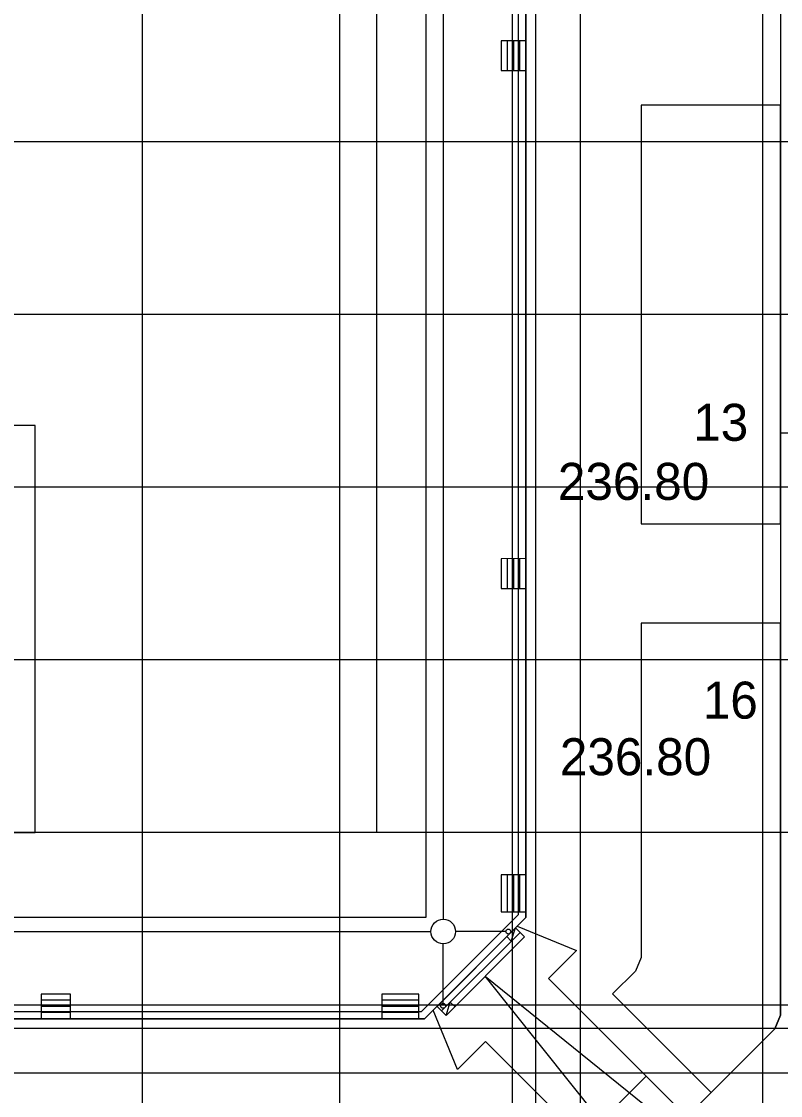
# Model space of a CAD drawing. Extents: x -264031 to -263588, y -1242281 to -1242059.
# Drawn here: x -263832.36 to -263801.59, y -1242227.54 to -1242184 of the extents above; entities that cross this region are included whole.
import ezdxf

# ---------------------------------------------------------------- set-up
doc = ezdxf.new("R2010")
doc.units = 0
for name, color, linetype in [('HESCON_OSI_STAVBY_KFA', 7, 'Continuous'), ('KFA_2D_SITUACIA_DSP', 7, 'Continuous'), ('KFA_BODY_CISLO', 7, 'Continuous'), ('KFA_BODY_VYSKA', 7, 'Continuous')]:
    doc.layers.add(name, color=color, linetype=linetype)

msp = doc.modelspace()

# ---------------------------------------------------------------- linework, layer by layer
at = {"layer": 'HESCON_OSI_STAVBY_KFA'}
for p, q in [((-263827.468, -1242083.237), (-263827.468, -1242246.707)), ((-263819.468, -1242083.237), (-263819.468, -1242246.707)), ((-263812.468, -1242083.237), (-263812.468, -1242246.707)), ((-263811.518, -1242083.237), (-263811.518, -1242246.707)), ((-263809.718, -1242083.237), (-263809.718, -1242246.707)), ((-263802.318, -1242083.237), (-263802.318, -1242246.707)), ((-263792.653, -1242188.882), (-263909.343, -1242188.882)), ((-263792.653, -1242195.882), (-263917.263, -1242195.882)), ((-263792.653, -1242202.882), (-263909.343, -1242202.882)), ((-263792.653, -1242209.882), (-263909.343, -1242209.882)), ((-263792.653, -1242216.882), (-263911.523, -1242216.882)), ((-263792.653, -1242223.882), (-263911.523, -1242223.882)), ((-263792.653, -1242224.832), (-263911.523, -1242224.832)), ((-263792.653, -1242226.632), (-263911.523, -1242226.632))]:
    msp.add_line(p, q, dxfattribs=at)
at = {"layer": 'KFA_2D_SITUACIA_DSP'}
for p, q in [((-263815.263, -1242164.687), (-263815.263, -1242220.396)), ((-263811.918, -1242184.782), (-263812.918, -1242184.782)), ((-263812.918, -1242184.782), (-263812.918, -1242185.982)), ((-263812.668, -1242184.782), (-263812.668, -1242185.982)), ((-263812.418, -1242184.782), (-263812.418, -1242185.982)), ((-263812.168, -1242184.782), (-263812.168, -1242185.982)), ((-263812.918, -1242185.982), (-263811.918, -1242185.982)), ((-263807.243, -1242187.394), (-263807.243, -1242204.369)), ((-263801.593, -1242187.394), (-263807.243, -1242187.394)), ((-263801.593, -1242204.369), (-263801.593, -1242187.394)), ((-263801.593, -1242200.682), (-263800.593, -1242200.682)), ((-263807.243, -1242204.369), (-263801.593, -1242204.369)), ((-263811.924, -1242205.773), (-263812.918, -1242205.782)), ((-263812.918, -1242205.782), (-263812.918, -1242206.982)), ((-263812.668, -1242205.782), (-263812.668, -1242206.982)), ((-263812.418, -1242205.782), (-263812.418, -1242206.982)), ((-263812.168, -1242205.782), (-263812.168, -1242206.982)), ((-263812.918, -1242206.982), (-263811.924, -1242206.991)), ((-263807.243, -1242208.394), (-263807.243, -1242221.942)), ((-263801.593, -1242208.394), (-263807.243, -1242208.394)), ((-263801.593, -1242224.282), (-263801.593, -1242208.394)), ((-263811.939, -1242218.592), (-263812.918, -1242218.592)), ((-263812.918, -1242218.592), (-263812.918, -1242220.092)), ((-263812.668, -1242218.592), (-263812.668, -1242220.092)), ((-263812.418, -1242218.592), (-263812.418, -1242220.092)), ((-263812.168, -1242218.592), (-263812.168, -1242220.092)), ((-263812.918, -1242220.092), (-263811.918, -1242220.092)), ((-263815.516, -1242223.929), (-263812.335, -1242220.747)), ((-263812.506, -1242221.283), (-263812.335, -1242220.747)), ((-263812.151, -1242220.931), (-263812.335, -1242220.747)), ((-263851.668, -1242220.896), (-263815.763, -1242220.896)), ((-263815.334, -1242224.112), (-263812.152, -1242220.929)), ((-263811.968, -1242221.113), (-263815.15, -1242224.295)), ((-263812.725, -1242220.896), (-263814.763, -1242220.896)), ((-263812.504, -1242221.284), (-263812.688, -1242221.101)), ((-263811.968, -1242221.113), (-263812.152, -1242220.929)), ((-263815.27, -1242223.809), (-263815.264, -1242221.396)), ((-263807.243, -1242221.942), (-263807.472, -1242222.496)), ((-263807.472, -1242222.496), (-263808.4, -1242223.424)), ((-263830.369, -1242223.432), (-263831.567, -1242223.432)), ((-263831.567, -1242223.432), (-263831.567, -1242224.432)), ((-263830.369, -1242223.682), (-263831.567, -1242223.682)), ((-263830.369, -1242224.432), (-263830.369, -1242223.432)), ((-263816.259, -1242223.432), (-263817.757, -1242223.432)), ((-263817.757, -1242223.432), (-263817.757, -1242224.432)), ((-263816.259, -1242223.682), (-263817.757, -1242223.682)), ((-263816.259, -1242224.432), (-263816.259, -1242223.432)), ((-263815.15, -1242224.295), (-263814.98, -1242223.758)), ((-263814.797, -1242223.942), (-263814.98, -1242223.758)), ((-263808.4, -1242223.424), (-263804.405, -1242227.419)), ((-263830.369, -1242223.932), (-263831.567, -1242223.932)), ((-263830.369, -1242224.182), (-263831.567, -1242224.182)), ((-263816.259, -1242223.932), (-263817.757, -1242223.932)), ((-263816.259, -1242224.182), (-263817.757, -1242224.182)), ((-263815.333, -1242224.113), (-263815.516, -1242223.929)), ((-263815.15, -1242224.295), (-263815.334, -1242224.112)), ((-263801.822, -1242224.837), (-263801.593, -1242224.282)), ((-263804.405, -1242227.419), (-263801.822, -1242224.837))]:
    msp.add_line(p, q, dxfattribs=at)
for points in [[(-263909.043, -1242125.432), (-263902.343, -1242125.432), (-263902.343, -1242104.482), (-263902.112, -1242103.927), (-263898.54, -1242100.355), (-263895.995, -1242097.81), (-263892.423, -1242094.238), (-263891.868, -1242094.007), (-263812.071, -1242094.007), (-263811.513, -1242094.238), (-263801.823, -1242103.927), (-263801.593, -1242104.482), (-263801.593, -1242224.282), (-263801.824, -1242224.838), (-263805.392, -1242228.407)], [(-263811.918, -1242108.434), (-263811.918, -1242220.33), (-263812.262, -1242220.675), (-263809.862, -1242221.669), (-263810.999, -1242222.806), (-263807.039, -1242226.765), (-263809.585, -1242229.311), (-263813.545, -1242225.351), (-263814.681, -1242226.488), (-263815.675, -1242224.088), (-263816.02, -1242224.432), (-263887.916, -1242224.432)], [(-263807.941, -1242230.956), (-263813.544, -1242225.352), (-263814.681, -1242226.488), (-263815.675, -1242224.088), (-263812.262, -1242220.675)], [(-263812.262, -1242220.675), (-263809.863, -1242221.669), (-263810.999, -1242222.806), (-263805.392, -1242228.407)], [(-263803.204, -1242235.693), (-263813.559, -1242222.704), (-263800.652, -1242233.141)]]:
    msp.add_lwpolyline(points, dxfattribs=at)
for points in [[(-263816.02, -1242224.432), (-263811.918, -1242220.33), (-263811.918, -1242108.434), (-263816.02, -1242104.332), (-263887.916, -1242104.332), (-263892.018, -1242108.434), (-263892.018, -1242147.332), (-263893.618, -1242147.332), (-263893.618, -1242162.382), (-263894.718, -1242162.382), (-263894.718, -1242166.382), (-263893.618, -1242166.382), (-263893.618, -1242181.432), (-263892.018, -1242181.432), (-263892.018, -1242220.33), (-263887.916, -1242224.432)], [(-263816.144, -1242224.132), (-263812.218, -1242220.206), (-263812.218, -1242108.558), (-263816.144, -1242104.632), (-263887.792, -1242104.632), (-263891.718, -1242108.558), (-263891.718, -1242147.632), (-263893.318, -1242147.632), (-263893.318, -1242162.682), (-263894.418, -1242162.682), (-263894.418, -1242166.082), (-263893.318, -1242166.082), (-263893.318, -1242181.132), (-263891.718, -1242181.132), (-263891.718, -1242220.206), (-263887.792, -1242224.132)], [(-263887.968, -1242108.434), (-263815.968, -1242108.434), (-263815.968, -1242220.33), (-263887.968, -1242220.33)], [(-263885.968, -1242111.882), (-263817.968, -1242111.882), (-263817.968, -1242216.882), (-263885.968, -1242216.882)], [(-263801.593, -1242187.394), (-263807.243, -1242187.394), (-263807.243, -1242204.369), (-263801.593, -1242204.369)], [(-263831.808, -1242200.382), (-263872.128, -1242200.382), (-263872.128, -1242216.882), (-263831.808, -1242216.882)], [(-263801.593, -1242208.394), (-263807.243, -1242208.394), (-263807.243, -1242221.942), (-263807.472, -1242222.496), (-263808.4, -1242223.424), (-263804.405, -1242227.419), (-263801.822, -1242224.837), (-263801.593, -1242224.282)], [(-263812.688, -1242221.101), (-263812.506, -1242221.283), (-263812.335, -1242220.747)], [(-263814.98, -1242223.758), (-263815.334, -1242224.112), (-263815.15, -1242224.295)]]:
    msp.add_lwpolyline(points, close=True, dxfattribs=at)
for centre, radius in [((-263815.263, -1242220.896), 0.5), ((-263812.625, -1242220.896), 0.1), ((-263815.27, -1242223.909), 0.1)]:
    msp.add_circle(centre, radius, dxfattribs=at)

# ---------------------------------------------------------------- texts
at = {"layer": 'KFA_BODY_CISLO'}
for s, p in [('13', (-263805.132, -1242200.999)), ('16', (-263804.744, -1242212.264))]:
    msp.add_text(s, height=1.5, dxfattribs=at).set_placement(p)
at = {"layer": 'KFA_BODY_VYSKA'}
for p in [(-263810.618, -1242203.394), (-263810.538, -1242214.557)]:
    msp.add_text('236.80', height=1.5, dxfattribs=at).set_placement(p)

doc.saveas('drawing.dxf')
